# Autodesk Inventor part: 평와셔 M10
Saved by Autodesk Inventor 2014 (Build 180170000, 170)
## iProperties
Created: 2026-06
Part Number: 평와셔 M10
Material: 일반
Document SubType Name: Modeling
Designer: dg
Density: 1 g/cm^3
Appearance: 기본값
Author: dg
Author: jhkim
Description: 평면 와셔
Creation Date: 2026-05-29
Sending System: Autodesk Inventor 2027
Preprocessor: ST-DEVELOPER v20.1
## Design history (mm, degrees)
node "평와셔 M101"
body "Solid1"
node "기준1"
